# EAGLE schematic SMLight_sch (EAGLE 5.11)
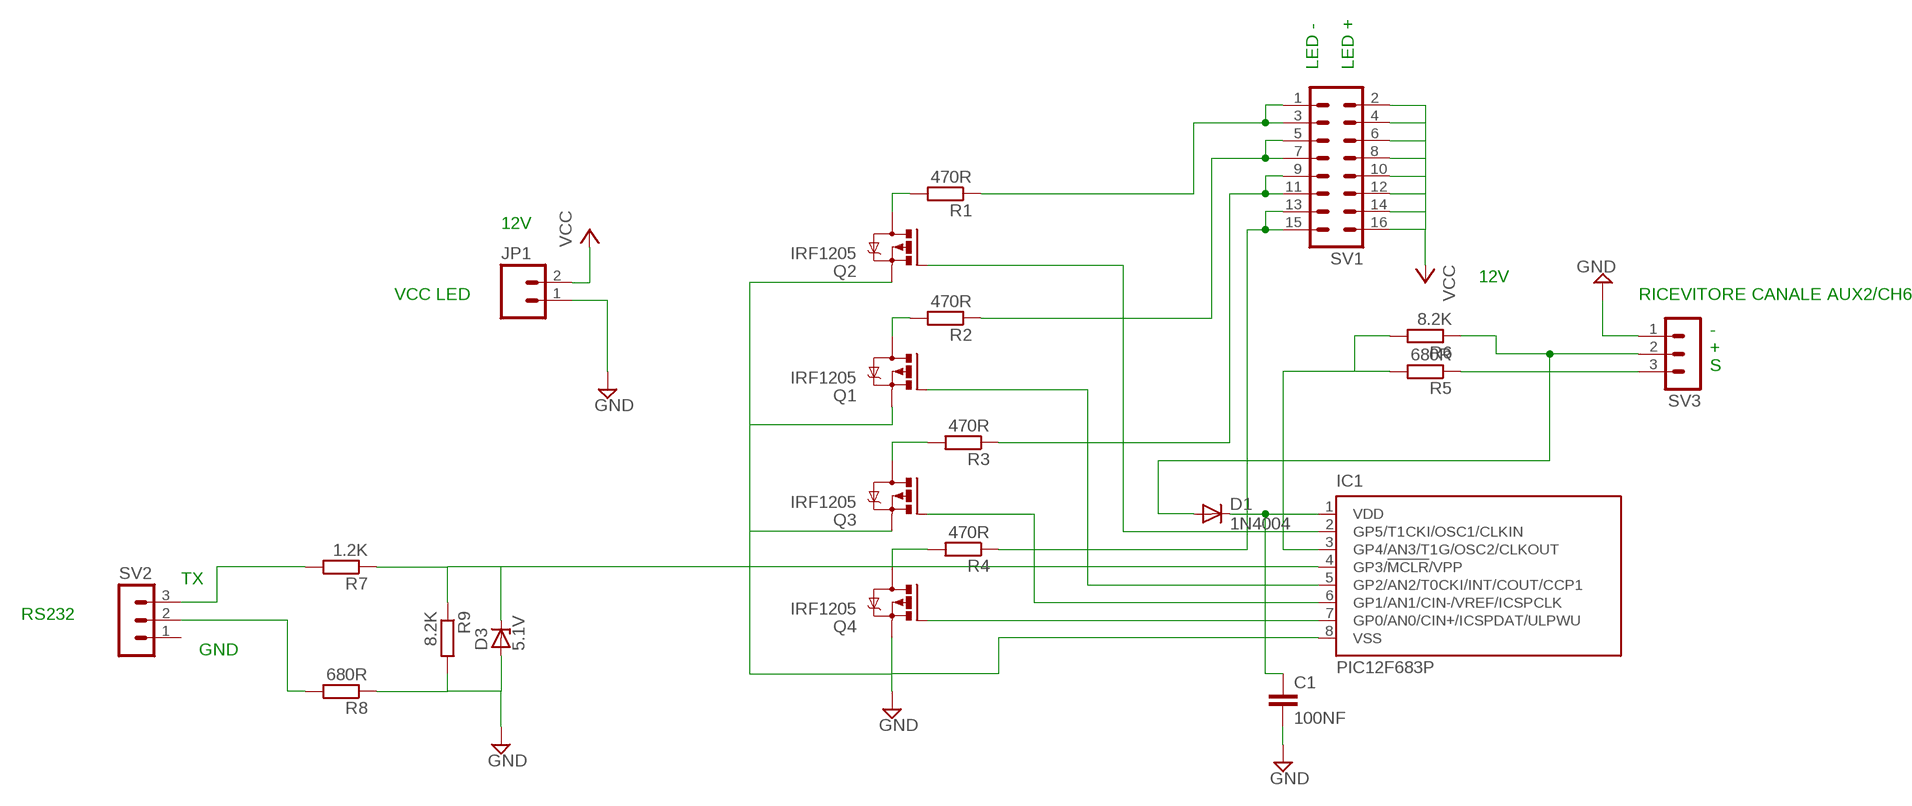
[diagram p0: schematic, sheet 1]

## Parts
C1  100NF  C-EUC1206K  [C1206K]
D1  1N4004  [DO41-10]
D3  5.1V  ZENER-DIODESOD80C  [SOD80C]
IC1  PIC12F683P  [DIL8]
JP1  M02  [1X02_LONGPADS]
Q1  IRF1205  IRFR5305  [D-PAK_TO252AA]
Q2  IRF1205  IRFR5305  [D-PAK_TO252AA]
Q3  IRF1205  IRFR5305  [D-PAK_TO252AA]
Q4  IRF1205  IRFR5305  [D-PAK_TO252AA]
R1  470R  R-EU_R1206  [R1206]
R2  470R  R-EU_R1206  [R1206]
R3  470R  R-EU_R1206  [R1206]
R4  470R  R-EU_R1206  [R1206]
R5  680R  R-EU_R1206  [R1206]
R6  8.2K  R-EU_R1206  [R1206]
R7  1.2K  R-EU_R1206  [R1206]
R8  680R  R-EU_R1206  [R1206]
R9  8.2K  R-EU_R1206  [R1206]
SV1  MA08-2W  [MA08-2W]
SV2  MA03-1  [MA03-1]
SV3  MA03-1  [MA03-1]

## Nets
GND: C1.2 D3.A IC1.8(VSS) JP1.1 Q1.3(S) Q2.3(S) Q3.3(S) Q4.3(S) R8.1 R9.2 SV3.1
N$1: C1.1 D1.C IC1.1(VDD)
N$2: IC1.3(GP4/AN3/T1G/OSC2/CLKOUT) R5.2 R6.2
N$3: R4.1 SV1.13 SV1.15
N$4: R3.1 SV1.9 SV1.11
N$5: R2.1 SV1.5 SV1.7
N$6: R1.1 SV1.1 SV1.3
N$7: Q3.4(D) R3.2
N$8: Q4.4(D) R4.2
N$9: Q1.4(D) R2.2
N$10: Q2.4(D) R1.2
N$11: R5.1 SV3.3
N$12: D1.A R6.1 SV3.2
N$13: D3.C IC1.4(GP3/!MCLR!/VPP) R7.1 R9.1
N$14: IC1.2(GP5/T1CKI/OSC1/CLKIN) Q2.1(G)
N$15: IC1.7(GP0/AN0/CIN+/ICSPDAT/ULPWU) Q4.1(G)
N$16: IC1.6(GP1/AN1/CIN-/VREF/ICSPCLK) Q3.1(G)
N$17: IC1.5(GP2/AN2/T0CKI/INT/COUT/CCP1) Q1.1(G)
N$20: R7.2 SV2.3
N$21: R8.2 SV2.2
VCC [VCC]: JP1.2 SV1.2 SV1.4 SV1.6 SV1.8 SV1.10 SV1.12 SV1.14 SV1.16
Unconnected: SV2.1

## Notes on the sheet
- LED - | LED +
- 12V
- 12V
- VCC LED | RICEVITORE CANALE AUX2/CH6
- -
- +
- S
- TX
- RS232
- GND

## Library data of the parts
C1 = rcl:C-EU: CAPACITOR, European symbol
D1 = diode:1N4004: DIODE
D3 = diode:ZENER-DIODE: Z-Diode
IC1 = microchip:PIC12F683: 8-Pin Flash-Based, 8-Bit CMOS Microcontrollers with nanoWatt Technology Source: http://ww1.microchip.com/downloads/en/DeviceDoc/41211D_.pdf; MF: MICROCHIP; MPN: PIC12F683-I/P; OC_FARNELL: 9759034; OC_NEWARK: 89H0442
JP1 = SparkFun:M02: Header 2
Q1-Q4 = transistor-power:IRF?5305: HEXFET Power MOSFET Source: http://www.irf.com/product-info/datasheets/data/irfr5305pbf.pdf
R1-R9 = rcl:R-EU_: RESISTOR, European symbol
SV1 = con-lstb:MA08-2W: PIN HEADER; OC_FARNELL: unknown; OC_NEWARK: unknown
SV2 SV3 = con-lstb:MA03-1: PIN HEADER; OC_FARNELL: unknown; OC_NEWARK: unknown

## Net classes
0 default: width 0.381 mm, clearance 0.305 mm
1 VCC: width 0.508 mm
